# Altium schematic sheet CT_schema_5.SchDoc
size 274 x 160 mm
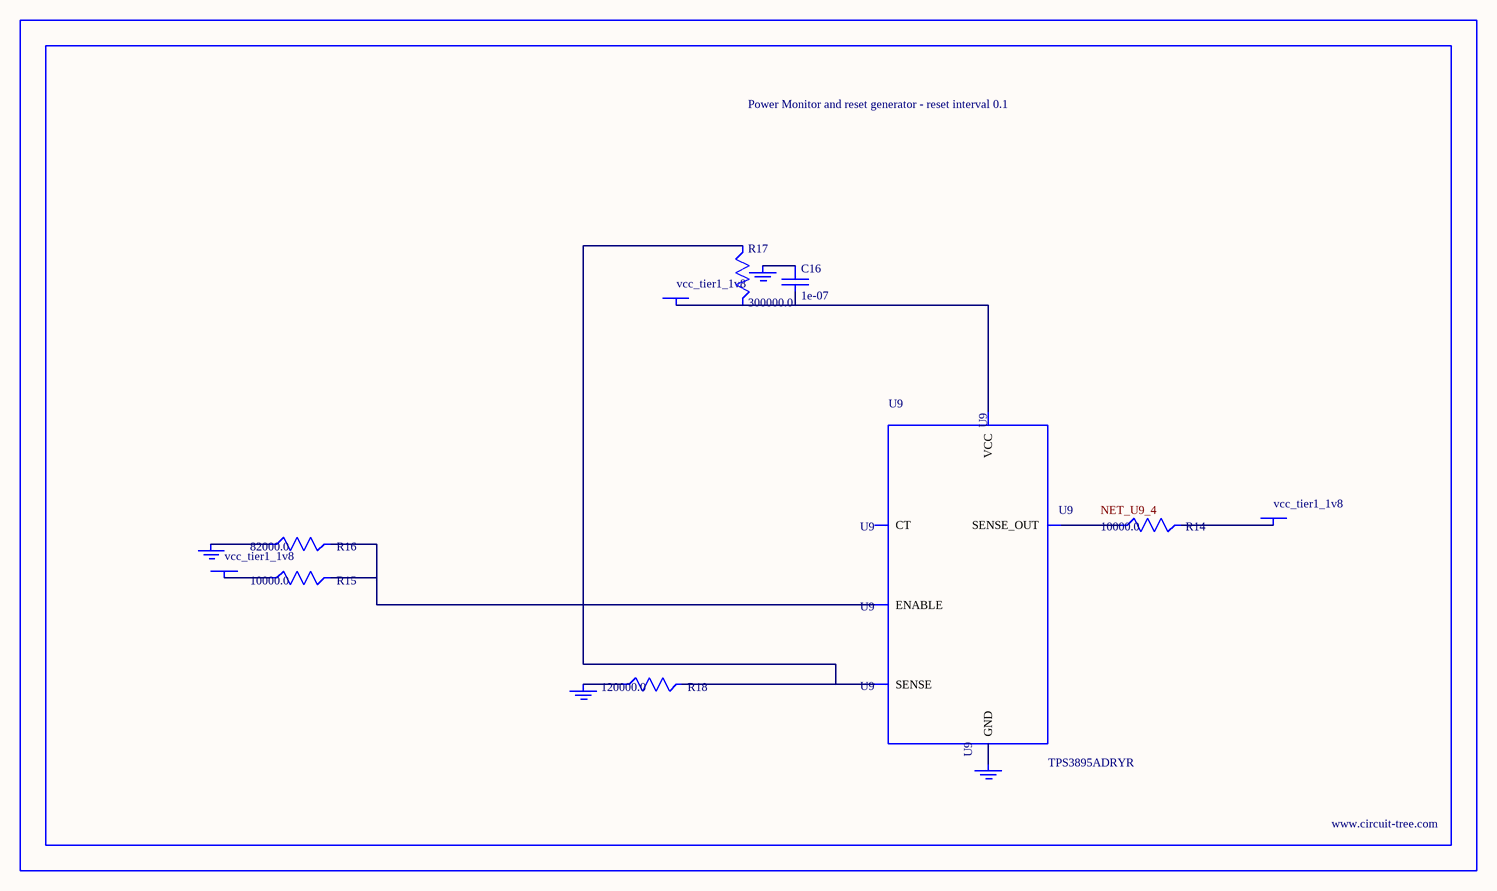
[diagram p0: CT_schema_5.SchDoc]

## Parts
BORDER4  (no value)
C16  1e-07  [C0402]
GND_INSTANCE_4_0  (no value)
GND_INSTANCE_4_1  (no value)
GND_INSTANCE_4_2  (no value)
GND_INSTANCE_4_3  (no value)
POWER_INSTANCE_4_0  vcc_tier1_1v8
POWER_INSTANCE_4_1  vcc_tier1_1v8
POWER_INSTANCE_4_2  vcc_tier1_1v8
R14  10000.0  [R0603]
R15  10000.0  [R0603]
R16  82000.0  [R0603]
R17  300000.0  [R0603]
R18  120000.0  [R0603]
U9  TPS3895ADRYR  [SON-6]

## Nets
NetC16_1: C16.1 GND_INSTANCE_4_2.0(GND)
NetC16_2: C16.2 POWER_INSTANCE_4_2.0(PWR) R17.2 U9.6(VCC)
NetGND_INSTANCE_4_0_0: GND_INSTANCE_4_0.0(GND) R16.1
NetGND_INSTANCE_4_1_0: GND_INSTANCE_4_1.0(GND) R18.1
NetGND_INSTANCE_4_3_0: GND_INSTANCE_4_3.0(GND) U9.2(GND)
NetPOWER_INSTANCE_4_0_0: POWER_INSTANCE_4_0.0(PWR) R15.1
NetPOWER_INSTANCE_4_1_0: POWER_INSTANCE_4_1.0(PWR) R14.2
NetR14_1: R14.1 U9.4(SENSE_OUT)
NetR15_2: R15.2 R16.2 U9.1(ENABLE)
NetR17_1: R17.1 R18.2 U9.3(SENSE)

Not connected (* = marked no-connect by the designer): U9 5(CT)

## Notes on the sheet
- Labels drawn without touching a wire or pin: NET_U9_4

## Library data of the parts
BORDER4 = BORDER_PAGE4
C16 = C0402C104K3RACTU
GND_INSTANCE_4_0-GND_INSTANCE_4_3 = GND
POWER_INSTANCE_4_0-POWER_INSTANCE_4_2 = PWR
R14 R15 = RC0603JR-0710KL
R16 = RC0603JR-0782KL
R17 = RC0603JR-07300KL
R18 = RC0603JR-07120KL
